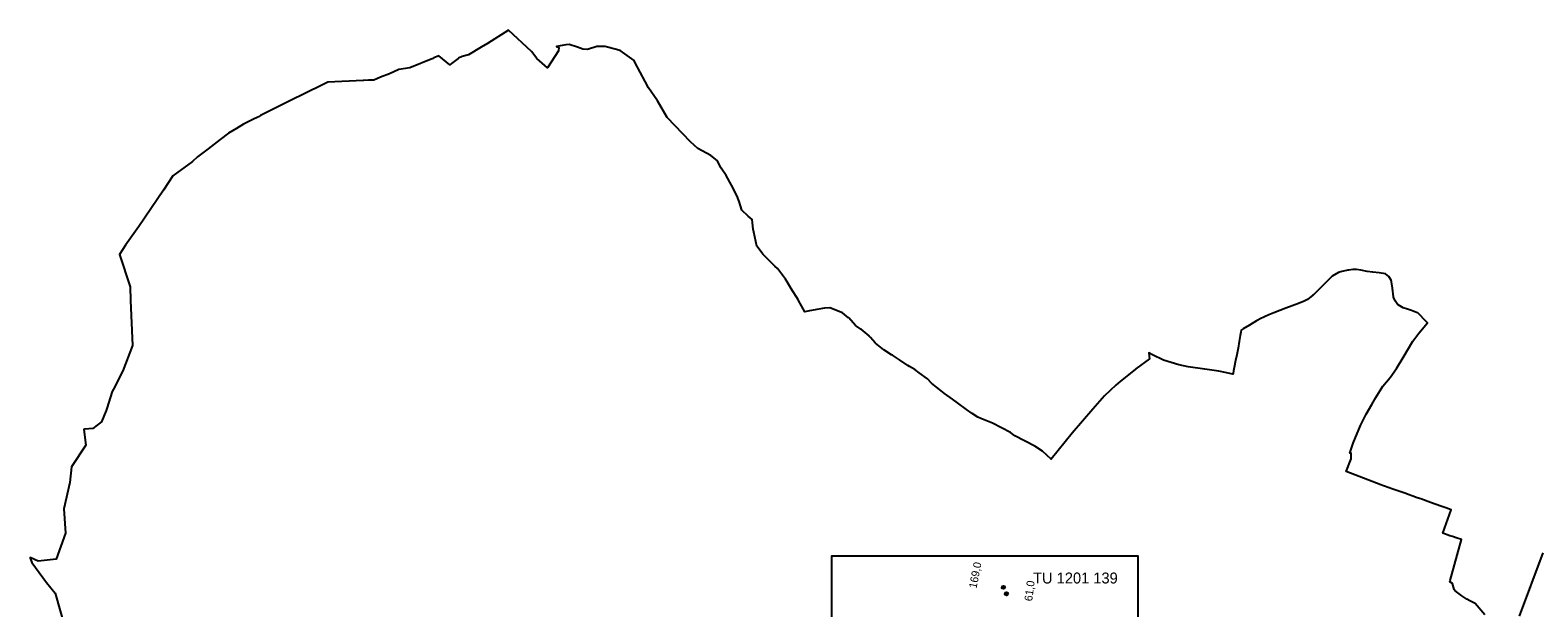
# Model space of a CAD drawing. Extents: x -661028 to -488604, y -1150850 to -1117549.
# Drawn here: x -661028 to -657588, y -1148318 to -1147001 of the extents above; entities that cross this region are included whole.
import ezdxf

# ---------------------------------------------------------------- set-up
doc = ezdxf.new("R2010")
doc.units = 0
for name, color, linetype in [('Polygon ku', 7, 'Continuous'), ('Ramecky', 7, 'Continuous'), ('Vrstva 7', 7, 'Continuous')]:
    doc.layers.add(name, color=color, linetype=linetype)

msp = doc.modelspace()

# ---------------------------------------------------------------- linework, layer by layer
at = {"layer": 'Polygon ku'}
for points in [[(-657708.7, -1148333.7), (-657731, -1148308.1), (-657734, -1148306.7), (-657743.1, -1148302.1), (-657750.1, -1148298.6), (-657761.7, -1148290.3), (-657770.6, -1148283.9), (-657777.8, -1148278.7), (-657778.7, -1148276), (-657783.1, -1148262.5), (-657789.2, -1148259), (-657788.2, -1148255.4), (-657762.2, -1148162.1), (-657771.8, -1148158.9), (-657782.8, -1148155.6), (-657788.7, -1148153.7), (-657804.9, -1148148.1), (-657785.6, -1148094.5), (-657797.6, -1148090.3), (-657807.2, -1148086.9), (-657822.4, -1148081.5), (-657832.9, -1148077.7), (-657855.2, -1148069.8), (-657863.7, -1148066.8), (-657872.9, -1148063.5), (-657881.8, -1148060.4), (-657891.9, -1148056.8), (-657921.4, -1148046.3), (-657925.1, -1148045), (-657942.8, -1148038.7), (-657946.2, -1148037.5), (-658025.3, -1148006.9), (-658014.1, -1147978.1), (-658013.9, -1147974.7), (-658013.9, -1147970.9), (-658014.3, -1147965.5), (-658016.7, -1147965.6), (-658009.2, -1147942.2), (-657992.9, -1147901.9), (-657979.8, -1147876.2), (-657966.6, -1147854.2), (-657957.5, -1147838.1), (-657942.1, -1147812.2), (-657925, -1147792.6), (-657910.2, -1147772.1), (-657895.5, -1147747.4), (-657873.6, -1147709.9), (-657859.9, -1147691.7), (-657839.7, -1147668.2), (-657841.8, -1147666), (-657861.9, -1147645.3), (-657865, -1147644.2), (-657876.3, -1147640.3), (-657885.8, -1147637), (-657895, -1147633.7), (-657906.7, -1147627.2), (-657907.3, -1147626.9), (-657913.3, -1147618.3), (-657913.4, -1147617.9), (-657917.1, -1147609.6), (-657917.5, -1147608.5), (-657919.6, -1147589.4), (-657922.2, -1147574.5), (-657922.8, -1147571.1), (-657928, -1147562.5), (-657935.9, -1147556.1), (-657950.2, -1147554.3), (-657964.5, -1147552.6), (-657977.8, -1147550.9), (-657992.1, -1147548.3), (-658001.5, -1147546.5), (-658007.5, -1147546.7), (-658010.2, -1147546.8), (-658019.6, -1147548), (-658021.8, -1147548.3), (-658024.9, -1147548.9), (-658035.4, -1147550.9), (-658042.9, -1147553), (-658057.6, -1147561.7), (-658078.5, -1147582.7), (-658100, -1147604), (-658101.3, -1147605), (-658113.7, -1147614.6), (-658122.4, -1147619.8), (-658132.3, -1147623.5), (-658134.4, -1147624.3), (-658163.2, -1147635), (-658190.4, -1147645.2), (-658202.1, -1147649.5), (-658211.9, -1147654.4), (-658221.6, -1147659.3), (-658227.3, -1147662.1), (-658229.9, -1147663.7), (-658246, -1147673.4), (-658260.2, -1147682), (-658265.1, -1147684.9), (-658265.8, -1147689.2), (-658267.1, -1147696.8), (-658269.5, -1147711), (-658272, -1147725.8), (-658275, -1147740.9), (-658277.7, -1147753.9), (-658280.9, -1147770), (-658282.4, -1147777.5), (-658283.5, -1147782.9), (-658283.9, -1147785.3), (-658301.7, -1147781.1), (-658315.8, -1147778.7), (-658347.6, -1147774.1), (-658385.6, -1147768.5), (-658407.5, -1147764), (-658442.5, -1147752.9), (-658467.1, -1147741.2), (-658476, -1147736.9), (-658475.1, -1147744.2), (-658474.4, -1147750.2), (-658505.7, -1147772.9), (-658506.5, -1147773.5), (-658522.3, -1147786.4), (-658540.5, -1147801.3), (-658551.3, -1147810.1), (-658576.8, -1147834.9), (-658582.2, -1147841), (-658603.6, -1147864.9), (-658650.3, -1147920), (-658698.8, -1147978.8), (-658718.1, -1147960.9), (-658735.6, -1147949.2), (-658781.3, -1147925.5), (-658791.3, -1147918.2), (-658832.5, -1147897), (-658858.7, -1147886.2), (-658865.7, -1147883.4), (-658879.1, -1147874.5), (-658891.9, -1147866.1), (-658912.4, -1147850.4), (-658923.5, -1147842.3), (-658941.7, -1147829.1), (-658949.4, -1147823.5), (-658960, -1147815), (-658971.9, -1147805.6), (-658981, -1147796), (-658999.4, -1147782.1), (-659009.9, -1147774.3), (-659021.5, -1147767.5), (-659025.4, -1147765.3), (-659045, -1147752.4), (-659060.9, -1147742), (-659062.6, -1147740.9), (-659080.5, -1147729.7), (-659099.2, -1147714.8), (-659100.3, -1147713.5), (-659110.9, -1147701.4), (-659112.8, -1147699.2), (-659114.2, -1147697.6), (-659132.5, -1147682.9), (-659133.1, -1147682.4), (-659142.5, -1147675.9), (-659144.8, -1147674.3), (-659160.6, -1147657), (-659161.3, -1147656.4), (-659174.4, -1147645.2), (-659203.3, -1147633.8), (-659215.7, -1147634.3), (-659233.5, -1147637.7), (-659254, -1147641.6), (-659260.6, -1147642.9), (-659268.1, -1147629.2), (-659274.8, -1147616.9), (-659275.1, -1147616.5), (-659292.3, -1147588.9), (-659301.3, -1147574.6), (-659305, -1147568.6), (-659309.4, -1147562.8), (-659318.6, -1147550.2), (-659323.1, -1147544.2), (-659328.8, -1147538.6), (-659345.4, -1147522.6), (-659353.6, -1147514.2), (-659356.6, -1147511.2), (-659365.1, -1147500.1), (-659370.3, -1147493.2), (-659377.3, -1147461), (-659378.7, -1147454.4), (-659378.8, -1147454.3), (-659380, -1147440), (-659380.6, -1147432.8), (-659389.7, -1147424.7), (-659404.8, -1147411.2), (-659410.9, -1147391.6), (-659413.3, -1147383.8), (-659413.9, -1147382.6), (-659428.1, -1147354.2), (-659440.2, -1147332.4), (-659451.5, -1147315.2), (-659452.2, -1147313.9), (-659460.4, -1147297.6), (-659474.8, -1147286.9), (-659504.6, -1147270.8), (-659521.5, -1147255.7), (-659574.9, -1147200.1), (-659597, -1147161.7), (-659598.4, -1147159.6), (-659617.6, -1147131.9), (-659625.4, -1147117.5), (-659647.6, -1147075.3), (-659650.3, -1147070.1), (-659677, -1147051), (-659682.2, -1147047.3), (-659711.1, -1147039.6), (-659716.4, -1147038.2), (-659735.2, -1147038), (-659756.4, -1147044.7), (-659766.9, -1147044.1), (-659779.6, -1147039.7), (-659798.5, -1147033.1), (-659806.3, -1147034.4), (-659827.1, -1147037.8), (-659822.1, -1147040.4), (-659823, -1147047.7), (-659847.8, -1147086.8), (-659872.1, -1147065.1), (-659884.4, -1147049.2), (-659936.6, -1147000.8), (-659985, -1147030.8), (-659999.1, -1147039.8), (-660028.2, -1147057), (-660042.9, -1147061), (-660051.1, -1147064.6), (-660051.8, -1147065.2), (-660066.6, -1147076.7), (-660070.5, -1147079.8), (-660096.2, -1147059.6), (-660107, -1147064), (-660109.6, -1147065), (-660162.4, -1147086.3), (-660187.2, -1147090.5), (-660208.6, -1147100.1), (-660228.7, -1147108.2), (-660244.2, -1147114.4), (-660252.1, -1147114.8), (-660256.5, -1147115), (-660267.1, -1147115.5), (-660268.9, -1147115.6), (-660349.2, -1147119.4), (-660363.2, -1147126.4), (-660435.5, -1147161.9), (-660502.7, -1147195.7), (-660507.4, -1147198.1), (-660521.9, -1147205.3), (-660541.8, -1147215.3), (-660557.5, -1147224.9), (-660575.9, -1147235.3), (-660594.5, -1147249.9), (-660622.6, -1147271), (-660646.4, -1147289.7), (-660658.3, -1147299.9), (-660702.5, -1147333.2), (-660724.5, -1147365.7), (-660780.4, -1147448.4), (-660810.6, -1147491.3), (-660824.8, -1147512.2), (-660800.3, -1147585.7), (-660799.1, -1147617.1), (-660795, -1147719.5), (-660817.1, -1147777.5), (-660832, -1147806.9), (-660835.4, -1147813.7), (-660841.1, -1147824.8), (-660853.5, -1147863.3), (-660855.1, -1147868.3), (-660865.8, -1147893.6), (-660885.4, -1147909.1), (-660903.6, -1147910.9), (-660905.8, -1147911.1), (-660901.6, -1147946.9), (-660934.1, -1147996.8), (-660937.8, -1148032), (-660951.5, -1148092.6), (-660947.4, -1148147.9), (-660969, -1148207), (-661010.3, -1148211.4), (-661028.2, -1148203.3), (-661028.4, -1148204.5), (-661024.6, -1148214.4), (-660990.8, -1148259.9), (-660971.6, -1148284.7), (-660949.9, -1148359.5)], [(-657576.5, -1148192.9), (-657630.8, -1148336.7)]]:
    msp.add_lwpolyline(points, dxfattribs=at)
at = {"layer": 'Ramecky'}
msp.add_lwpolyline([(-659200, -1148700), (-658500, -1148700), (-658500, -1148200), (-659200, -1148200)], close=True, dxfattribs=at)
at = {"layer": 'Vrstva 7'}
for centre, radius in [((-658807.5, -1148271.3), 3.74), ((-658807.5, -1148271.3), 3.74), ((-658807.5, -1148271.3), 2.26), ((-658807.5, -1148271.3), 2.26), ((-658800.8, -1148286), 3.74), ((-658800.8, -1148286), 3.74), ((-658800.8, -1148286), 2.26), ((-658800.8, -1148286), 2.26)]:
    msp.add_circle(centre, radius, dxfattribs=at)

# ---------------------------------------------------------------- texts
at = {"layer": 'Ramecky'}
msp.add_text('TU 1201 139', height=25, dxfattribs=at).set_placement((-658739.9, -1148262.5))
at = {"layer": 'Vrstva 7'}
for s, rotation, p in [('169,0', 78.7684, (-658869, -1148274.8)), ('169,0', 78.7684, (-658869, -1148274.8)), ('61,0', 82.6614, (-658742, -1148303.7)), ('61,0', 82.6614, (-658742, -1148303.7))]:
    msp.add_text(s, height=18, rotation=rotation, dxfattribs=at).set_placement(p)

doc.saveas('drawing.dxf')
